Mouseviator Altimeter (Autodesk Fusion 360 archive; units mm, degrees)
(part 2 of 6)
sketch "Sketch1" plane through (-20, 10.05, 25) normal (0, -1, 0) x axis (1, 0, 0)
  line L1 (35.633, -31.4583) -> (38.9512, -31.4583)
  line L2 (35.3122, -31.4583) -> (35.633, -31.4583)
  line L3 (39.272, -31.4583) -> (35.3122, -31.4583)
  line L4 (38.9512, -31.4583) -> (39.272, -31.4583)
  line L5 (35.633, -28.5383) -> (35.3122, -28.5383)
  line L6 (38.9512, -28.5383) -> (35.633, -28.5383)
  line L7 (39.272, -28.5383) -> (38.9512, -28.5383)
  line L8 (35.3122, -28.5383) -> (39.272, -28.5383)
  line L9 (35.0708, -31.6363) -> (39.5135, -31.6363)
  line L10 (35.0708, -28.3602) -> (39.5135, -28.3602)
  line L11 (12.6239, -9.6591) -> (12.6239, -6.3409)
  line L12 (15.5439, -6.3409) -> (15.5439, -9.6591)
  line L13 (35.0124, -22.3491) -> (35.0004, -22.3785)
  line L14 (34.9323, -22.4564) -> (34.9111, -22.4657)
  line L15 (35.0979, -20.5925) -> (35.0505, -20.7749)
  line L16 (35.1569, -20.399) -> (35.0979, -20.5925)
  line L17 (36.6379, -21.3693) -> (36.6123, -21.2895)
  line L18 (34.97, -22.4255) -> (34.952, -22.443)
  line L19 (36.8842, -22.088) -> (36.8616, -22.0733)
  line L20 (36.5783, -21.1969) -> (36.5345, -21.0916)
  line L21 (36.6687, -21.4893) -> (36.6379, -21.3693)
  line L22 (36.7142, -21.799) -> (36.6929, -21.6882)
  line L23 (36.4146, -20.8483) -> (36.3364, -20.7116)
  line L24 (34.9578, -21.3696) -> (34.9526, -21.4836)
  line L25 (35.0129, -21.9844) -> (35.0308, -22.0958)
  line L26 (34.9677, -21.7892) -> (34.9793, -21.8532)
  line L27 (36.8182, -22.0307) -> (36.7977, -22.0028)
  line L28 (36.7431, -21.8932) -> (36.7142, -21.799)
  line L29 (37.806, -21.9706) -> (37.7866, -22.0028)
  line L30 (35.0359, -22.1943) -> (35.0294, -22.2789)
  line L31 (35.2212, -20.2151) -> (35.1569, -20.399)
  line L32 (34.9523, -21.5822) -> (34.9556, -21.666)
  line L33 (36.9302, -22.1041) -> (36.9071, -22.0983)
  line L34 (37.631, -22.1056) -> (37.4781, -22.1004)
  line L35 (37.7227, -22.0733) -> (37.7001, -22.088)
  line L36 (36.7782, -21.9706) -> (36.7431, -21.8932)
  line L37 (37.7001, -22.088) -> (37.6771, -22.0983)
  line L38 (37.4781, -22.1004) -> (37.2921, -22.0983)
  line L39 (37.7661, -22.0307) -> (37.7447, -22.0542)
  line L40 (36.6929, -21.6882) -> (36.6796, -21.5534)
  line L41 (36.6796, -21.5534) -> (36.6687, -21.4893)
  line L42 (36.2439, -20.5644) -> (36.137, -20.4092)
  line L43 (41.0503, -21.8878) -> (40.9731, -21.9719)
  line L44 (46.5349, -27.1956) -> (46.6729, -27.0478)
  line L45 (46.1507, -27.5452) -> (46.2718, -27.4445)
  line L46 (40.7882, -22.2157) -> (40.756, -22.2722)
  line L47 (40.4626, -22.6733) -> (40.4345, -22.6881)
  line L48 (36.5345, -21.0916) -> (36.4805, -20.9756)
  line L49 (45.0219, -28.1981) -> (45.0369, -28.1731)
  line L50 (45.8358, -27.767) -> (45.932, -27.7055)
  line L51 (41.6572, -21.3826) -> (41.5036, -21.4919)
  line L52 (40.1681, -22.6404) -> (39.9941, -22.5747)
  line L53 (37.8411, -21.8932) -> (37.806, -21.9706)
  line L54 (36.8395, -22.0542) -> (36.8182, -22.0307)
  line L55 (37.6771, -22.0983) -> (37.6541, -22.1041)
  line L56 (37.7447, -22.0542) -> (37.7227, -22.0733)
  line L57 (46.0368, -27.6322) -> (46.1507, -27.5452)
  line L58 (37.2921, -22.0983) -> (37.1061, -22.1004)
  line L59 (36.4805, -20.9756) -> (36.4146, -20.8483)
  line L60 (45.0564, -28.148) -> (45.0803, -28.1229)
  line L61 (45.0035, -28.271) -> (45.0052, -28.2473)
  line L62 (41.1407, -21.7973) -> (41.0503, -21.8878)
  line L63 (39.6142, -22.4255) -> (39.598, -22.404)
  line L64 (37.1061, -22.1004) -> (36.9533, -22.1056)
  line L65 (45.2665, -28.0054) -> (45.3719, -27.9652)
  line L66 (40.3809, -22.7046) -> (40.3559, -22.7064)
  line L67 (45.1086, -28.0982) -> (45.1787, -28.0502)
  line L68 (45.5023, -27.9287) -> (45.5635, -27.9067)
  line L69 (40.4345, -22.6881) -> (40.4072, -22.6985)
  line L70 (45.5635, -27.9067) -> (45.6764, -27.8557)
  line L71 (45.0052, -28.2473) -> (45.0114, -28.2229)
  line L72 (39.652, -22.4564) -> (39.6323, -22.443)
  line L73 (36.6123, -21.2895) -> (36.5783, -21.1969)
  line L74 (46.2718, -27.4445) -> (46.4006, -27.3279)
  line L75 (45.0369, -28.1731) -> (45.0564, -28.148)
  line L76 (41.5036, -21.4919) -> (41.3664, -21.5985)
  line L77 (36.7977, -22.0028) -> (36.7782, -21.9706)
  line L78 (37.6541, -22.1041) -> (37.631, -22.1056)
  line L79 (45.0114, -28.2229) -> (45.0219, -28.1981)
  line L80 (46.4006, -27.3279) -> (46.5349, -27.1956)
  line L81 (45.3719, -27.9652) -> (45.5023, -27.9287)
  line L82 (45.7505, -27.8166) -> (45.8358, -27.767)
  line L83 (37.7866, -22.0028) -> (37.7661, -22.0307)
  line L84 (36.9071, -22.0983) -> (36.8842, -22.088)
  line L85 (45.6764, -27.8557) -> (45.7505, -27.8166)
  line L86 (45.1787, -28.0502) -> (45.2665, -28.0054)
  line L87 (39.598, -22.404) -> (39.5838, -22.3785)
  line L88 (45.0803, -28.1229) -> (45.1086, -28.0982)
  line L89 (39.8185, -22.5131) -> (39.6732, -22.4657)
  line L90 (40.31, -22.6974) -> (40.1681, -22.6404)
  line L91 (40.6974, -22.3943) -> (40.6395, -22.4911)
  line L92 (45.932, -27.7055) -> (46.0368, -27.6322)
  line L93 (36.9533, -22.1056) -> (36.9302, -22.1041)
  line L94 (40.756, -22.2722) -> (40.6974, -22.3943)
  line L95 (40.8581, -22.1135) -> (40.7882, -22.2157)
  line L96 (40.9731, -21.9719) -> (40.9095, -22.0472)
  line L97 (36.8616, -22.0733) -> (36.8395, -22.0542)
  line L98 (40.3559, -22.7064) -> (40.3322, -22.704)
  line L99 (40.4914, -22.6541) -> (40.4626, -22.6733)
  line L100 (40.5801, -22.5698) -> (40.5207, -22.6305)
  line L101 (41.9942, -21.1728) -> (41.8267, -21.2723)
  line L102 (44.6267, -24.8888) -> (44.7002, -24.7841)
  line L103 (42.5014, -22.4249) -> (42.5294, -22.27)
  line L104 (44.938, -24.3736) -> (45.0189, -24.2034)
  line L105 (42.2262, -23.8286) -> (42.1059, -23.7343)
  line L106 (43.5976, -23.6623) -> (43.4963, -23.7149)
  line L107 (40.5207, -22.6305) -> (40.4914, -22.6541)
  line L108 (40.9095, -22.0472) -> (40.8581, -22.1135)
  line L109 (41.2462, -21.7002) -> (41.1407, -21.7973)
  line L110 (41.3664, -21.5985) -> (41.2462, -21.7002)
  line L111 (42.571, -21.9102) -> (42.5817, -21.7082)
  line L112 (42.0518, -23.6218) -> (42.0505, -23.5901)
  line L113 (42.0642, -23.6764) -> (42.0564, -23.6507)
  line L114 (42.3701, -23.9465) -> (42.2262, -23.8286)
  line L115 (42.47, -22.5648) -> (42.5014, -22.4249)
  line L116 (42.3693, -22.89) -> (42.4027, -22.7972)
  line L117 (39.9941, -22.5747) -> (39.8185, -22.5131)
  line L118 (42.0752, -23.699) -> (42.0642, -23.6764)
  line L119 (42.0505, -23.5901) -> (42.0527, -23.5556)
  line L120 (42.6436, -24.1837) -> (42.625, -24.1699)
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  parallel L8 L10
  dimension "d124" diameter = 18
  dimension "d189" = 0.3 (= "StepperTightness")
  dimension "d190" = 0.3 (= "d189")
extrude "Extrude1" new body sketch "Sketch1" to an object offset 1.25
sketch "Sketch1" plane through (14.0839, 18.05, 42) normal (0, -1, 0) x axis (-1, 0, 0)
  line L1 (21.46, 26.6591) -> (21.46, 23.3409)
  line L2 (18.54, 23.3409) -> (18.54, 26.6591)
  line L3 (25.078, 31.0517) -> (24.9341, 31.1697)
  line L4 (24.8138, 31.264) -> (24.797, 31.2799)
  line L5 (25.2093, 32.5734) -> (25.2373, 32.7283)
  line L6 (24.9341, 31.1697) -> (24.8138, 31.264)
  line L7 (25.3329, 30.8284) -> (25.2192, 30.9305)
  line L8 (24.0743, 33.3998) -> (23.9541, 33.2981)
  line L9 (25.261, 32.9005) -> (25.2789, 33.0881)
  line L10 (24.5346, 33.726) -> (24.3651, 33.6157)
  line L11 (25.2789, 33.0881) -> (25.2896, 33.2901)
  line L12 (24.7893, 31.5617) -> (24.8278, 31.6525)
  line L13 (24.3651, 33.6157) -> (24.2115, 33.5064)
  line L14 (24.2115, 33.5064) -> (24.0743, 33.3998)
  line L15 (24.7664, 31.4799) -> (24.7893, 31.5617)
  line L16 (25.1779, 32.4335) -> (25.2093, 32.5734)
  line L17 (24.9591, 31.8628) -> (24.9919, 31.919)
  line L18 (23.9541, 33.2981) -> (23.8486, 33.2009)
  line L19 (24.7021, 33.8255) -> (24.5346, 33.726)
  line L20 (25.2373, 32.7283) -> (25.261, 32.9005)
  line L21 (25.2192, 30.9305) -> (25.078, 31.0517)
  line L22 (25.0455, 32.0306) -> (25.0772, 32.1083)
  line L23 (25.2896, 33.2901) -> (25.2921, 33.4849)
  line L24 (24.9919, 31.919) -> (25.0455, 32.0306)
  line L25 (25.1448, 32.3099) -> (25.1779, 32.4335)
  line L26 (28.6945, 24.1572) -> (28.7916, 24.1746)
  line L27 (29.4726, 24.3941) -> (29.644, 24.4724)
  line L28 (29.1634, 25.7247) -> (29.0265, 25.7675)
  line L29 (29.4726, 25.6059) -> (29.3116, 25.6715)
  line L30 (24.7643, 31.3476) -> (24.7597, 31.3764)
  line L31 (28.1751, 24.1453) -> (28.2879, 24.147)
  line L32 (27.8469, 25.9926) -> (27.8371, 26.0144)
  line L33 (27.8371, 26.0144) -> (27.8317, 26.0368)
  line L34 (25.0772, 32.1083) -> (25.1106, 32.201)
  line L35 (28.6115, 24.1458) -> (28.6945, 24.1572)
  line L36 (29.644, 24.4724) -> (29.8242, 24.5641)
  line L37 (27.9289, 24.0832) -> (27.9599, 24.0985)
  line L38 (24.7597, 31.3764) -> (24.7584, 31.4082)
  line L39 (27.995, 25.8879) -> (27.9599, 25.9014)
  line L40 (28.2879, 24.147) -> (28.423, 24.1367)
  line L41 (29.9942, 25.3406) -> (29.8242, 25.4359)
  line L42 (28.7916, 25.8254) -> (28.6945, 25.8428)
  line L43 (28.488, 25.8636) -> (28.423, 25.8633)
  line L44 (27.8317, 26.0368) -> (27.8102, 26.1882)
  line L45 (27.995, 24.1121) -> (28.0773, 24.1332)
  line L46 (28.7916, 24.1746) -> (28.903, 24.1995)
  line L47 (29.0265, 25.7675) -> (28.903, 25.8005)
  line L48 (29.3116, 25.6715) -> (29.1634, 25.7247)
  line L49 (29.644, 25.5276) -> (29.4726, 25.6059)
  line L50 (24.7584, 31.4082) -> (24.7606, 31.4427)
  line L51 (27.9289, 25.9168) -> (27.902, 25.9337)
  line L52 (28.903, 25.8005) -> (28.7916, 25.8254)
  line L53 (27.8102, 26.1882) -> (27.78, 26.3718)
  line L54 (25.1106, 32.201) -> (25.1448, 32.3099)
  line L55 (24.8826, 31.751) -> (24.9591, 31.8628)
  line L56 (27.7456, 26.5546) -> (27.714, 26.7042)
  line L57 (27.861, 25.9718) -> (27.8469, 25.9926)
  line L58 (28.2879, 25.853) -> (28.1751, 25.8547)
  line L59 (24.7721, 31.3218) -> (24.7643, 31.3476)
  line L60 (27.9599, 24.0985) -> (27.995, 24.1121)
  line L61 (29.0265, 24.2325) -> (29.1634, 24.2753)
  line L62 (28.0773, 24.1332) -> (28.1751, 24.1453)
  line L63 (28.6115, 25.8542) -> (28.488, 25.8636)
  line L64 (24.8278, 31.6525) -> (24.8826, 31.751)
  line L65 (27.714, 26.7042) -> (27.7114, 26.7272)
  line L66 (24.797, 31.2799) -> (24.7831, 31.2992)
  line L67 (27.78, 26.3718) -> (27.7456, 26.5546)
  line L68 (27.902, 25.9337) -> (27.8794, 25.9521)
  line L69 (29.3116, 24.3285) -> (29.4726, 24.3941)
  line L70 (27.902, 24.0662) -> (27.9289, 24.0832)
  line L71 (27.8794, 24.0478) -> (27.902, 24.0662)
  line L72 (28.488, 24.1364) -> (28.6115, 24.1458)
  line L73 (27.8794, 25.9521) -> (27.861, 25.9718)
  line L74 (28.423, 24.1367) -> (28.488, 24.1364)
  line L75 (28.903, 24.1995) -> (29.0265, 24.2325)
  line L76 (29.1634, 24.2753) -> (29.3116, 24.3285)
  line L77 (28.0773, 25.8667) -> (27.995, 25.8879)
  line L78 (28.1751, 25.8547) -> (28.0773, 25.8667)
  line L79 (28.423, 25.8633) -> (28.2879, 25.853)
  line L80 (24.7606, 31.4427) -> (24.7664, 31.4799)
  line L81 (24.7831, 31.2992) -> (24.7721, 31.3218)
  line L82 (27.9599, 25.9014) -> (27.9289, 25.9168)
  line L83 (28.6945, 25.8428) -> (28.6115, 25.8542)
  line L84 (29.8242, 24.5641) -> (29.9942, 24.6594)
  line L85 (29.8242, 25.4359) -> (29.644, 25.5276)
  line L86 (29.3808, 22.0495) -> (29.2428, 22.1973)
  line L87 (27.2937, 21.4229) -> (27.3898, 21.4008)
  line L88 (27.8866, 23.0519) -> (27.8165, 23.0999)
  line L89 (28.2197, 21.1915) -> (28.3629, 21.1849)
  line L90 (27.78, 23.6282) -> (27.8102, 23.8117)
  line L91 (27.861, 24.0281) -> (27.8794, 24.0478)
  line L92 (27.3898, 21.4008) -> (27.4963, 21.3638)
  line L93 (28.7447, 22.6339) -> (28.6399, 22.7072)
  line L94 (28.6941, 21.1908) -> (28.8819, 21.2058)
  line L95 (27.7882, 23.1246) -> (27.7643, 23.1497)
  line L96 (28.5437, 22.7687) -> (28.4584, 22.8183)
  line L97 (27.0785, 21.4104) -> (27.1061, 21.4199)
  line L98 (29.0827, 21.2303) -> (29.275, 21.2617)
  line L99 (27.7448, 23.1748) -> (27.7298, 23.1998)
  line L100 (28.0798, 22.9669) -> (27.9744, 23.0071)
  line L101 (27.1715, 21.4305) -> (27.2092, 21.4312)
  line L102 (28.0923, 21.2028) -> (28.2197, 21.1915)
  line L103 (28.8587, 22.5469) -> (28.7447, 22.6339)
  line L104 (27.7643, 23.1497) -> (27.7448, 23.1748)
  line L105 (27.8102, 23.8117) -> (27.8317, 23.9631)
  line L106 (29.2428, 22.1973) -> (29.1085, 22.3296)
  line L107 (27.8317, 23.9631) -> (27.8371, 23.9856)
  line L108 (26.6659, 20.7602) -> (26.7467, 20.89)
  line L109 (26.6491, 20.7165) -> (26.6556, 20.7395)
  line L110 (27.0175, 21.3664) -> (27.0341, 21.3834)
  line L111 (28.5204, 21.1843) -> (28.6941, 21.1908)
  line L112 (27.0341, 21.3834) -> (27.0545, 21.3982)
  line L113 (27.9791, 21.2175) -> (28.0923, 21.2028)
  line L114 (27.6807, 21.2854) -> (27.8, 21.252)
  line L115 (27.8371, 23.9856) -> (27.8469, 24.0073)
  line L116 (27.4963, 21.3638) -> (27.6197, 21.308)
  line L117 (27.9744, 23.0071) -> (27.8866, 23.0519)
  line L118 (27.2092, 21.4312) -> (27.2937, 21.4229)
  line L119 (27.8165, 23.0999) -> (27.7882, 23.1246)
  line L120 (27.0047, 21.3471) -> (27.0175, 21.3664)
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extrude "Extrude1" new body sketch "Sketch1" to an object offset 1.25
work_plane "WorkPlane1" AlongDistance 0
sketch "Gear" plane through (-20, 10.05, 25) normal (0, -1, 0) x axis (1, 0, 0)
  line L1 (20.549, -33.1051) -> (20.5779, -33.1993)
  line L2 (23.566, -32.8848) -> (23.6174, -32.9511)
  line L3 (22.3049, -33.8984) -> (22.3233, -33.7561)
  line L4 (20.6235, -33.509) -> (20.6542, -33.629)
  line L5 (25.1106, -32.2011) -> (25.0771, -32.1083)
  line L6 (22.702, -32.4236) -> (22.876, -32.3579)
  line L7 (22.1352, -34.5993) -> (22.1942, -34.4058)
  line L8 (22.3811, -32.5326) -> (22.5264, -32.4852)
  line L9 (20.9557, -34.2867) -> (21.0482, -34.4339)
  line L10 (20.5779, -33.1993) -> (20.5992, -33.3101)
  line L11 (20.4526, -32.9441) -> (20.474, -32.9676)
  line L12 (23.6174, -32.9511) -> (23.681, -33.0264)
  line L13 (22.876, -32.3579) -> (23.0179, -32.3008)
  line L14 (23.1423, -32.3102) -> (23.1705, -32.325)
  line L15 (22.2416, -34.2234) -> (22.2782, -34.0535)
  line L16 (22.2562, -32.804) -> (22.2627, -32.7194)
  line L17 (23.0179, -32.3008) -> (23.0401, -32.2943)
  line L18 (21.0482, -34.4339) -> (21.1551, -34.589)
  line L19 (19.615, -32.9) -> (19.6381, -32.8941)
  line L20 (23.0888, -32.2937) -> (23.1151, -32.2998)
  line L21 (20.385, -32.9) -> (20.408, -32.9103)
  line L22 (23.2286, -32.3678) -> (23.288, -32.4285)
  line L23 (22.27, -32.6824) -> (22.2797, -32.6492)
  line L24 (22.2797, -32.6492) -> (22.2917, -32.6198)
  line L25 (22.3244, -33.209) -> (22.3128, -33.1451)
  line L26 (22.3395, -33.5147) -> (22.3398, -33.4161)
  line L27 (20.8116, -34.0227) -> (20.8775, -34.15)
  line L28 (22.3221, -32.5728) -> (22.3401, -32.5553)
  line L29 (20.6125, -33.4449) -> (20.6235, -33.509)
  line L30 (20.5139, -33.0277) -> (20.549, -33.1051)
  line L31 (22.3398, -33.4161) -> (22.3366, -33.3323)
  line L32 (22.2792, -33.0138) -> (22.2613, -32.9025)
  line L33 (22.3598, -32.5419) -> (22.3811, -32.5326)
  line L34 (22.3128, -33.1451) -> (22.2792, -33.0138)
  line L35 (22.2917, -32.6198) -> (22.3059, -32.5943)
  line L36 (23.681, -33.0264) -> (23.7582, -33.1105)
  line L37 (22.1942, -34.4058) -> (22.2416, -34.2234)
  line L38 (20.5992, -33.3101) -> (20.6125, -33.4449)
  line L39 (23.0401, -32.2943) -> (23.0638, -32.2919)
  line L40 (22.3233, -33.7561) -> (22.3343, -33.6287)
  line L41 (23.1993, -32.3442) -> (23.2286, -32.3678)
  line L42 (22.2627, -32.7194) -> (22.27, -32.6824)
  line L43 (22.2782, -34.0535) -> (22.3049, -33.8984)
  line L44 (20.8775, -34.15) -> (20.9557, -34.2867)
  line L45 (22.0709, -34.7832) -> (22.1352, -34.5993)
  line L46 (23.0638, -32.2919) -> (23.0888, -32.2937)
  line L47 (20.4945, -32.9955) -> (20.5139, -33.0277)
  line L48 (20.3619, -32.8941) -> (20.385, -32.9)
  line L49 (20.3389, -32.8927) -> (20.3619, -32.8941)
  line L50 (19.814, -32.8978) -> (20, -32.9)
  line L51 (25.2373, -32.7283) -> (25.2093, -32.5734)
  line L52 (24.0743, -33.3998) -> (24.2115, -33.5064)
  line L53 (22.3059, -32.5943) -> (22.3221, -32.5728)
  line L54 (22.5264, -32.4852) -> (22.702, -32.4236)
  line L55 (22.3366, -33.3323) -> (22.3244, -33.209)
  line L56 (22.3401, -32.5553) -> (22.3598, -32.5419)
  line L57 (22.3343, -33.6287) -> (22.3395, -33.5147)
  line L58 (22.2613, -32.9025) -> (22.2562, -32.804)
  line L59 (18.7233, -34.7507) -> (18.8449, -34.589)
  line L60 (20, -32.9) -> (20.186, -32.8978)
  line L61 (19.4008, -33.3101) -> (19.4221, -33.1993)
  line L62 (19.2424, -33.9067) -> (19.2862, -33.8013)
  line L63 (20.6542, -33.629) -> (20.6798, -33.7088)
  line L64 (20.7138, -33.8013) -> (20.7576, -33.9067)
  line L65 (20.408, -32.9103) -> (20.4305, -32.925)
  line L66 (21.1551, -34.589) -> (21.2767, -34.7507)
  line L67 (20.4305, -32.925) -> (20.4526, -32.9441)
  line L68 (17.7438, -32.804) -> (17.7387, -32.9025)
  line L69 (17.6605, -33.5147) -> (17.6657, -33.6287)
  line L70 (20.474, -32.9676) -> (20.4945, -32.9955)
  line L71 (18.8449, -34.589) -> (18.9518, -34.4339)
  line L72 (17.7083, -32.6198) -> (17.7203, -32.6492)
  line L73 (17.298, -32.4236) -> (17.4736, -32.4852)
  line L74 (16.8295, -32.325) -> (16.8577, -32.3102)
  line L75 (17.7373, -32.7194) -> (17.7438, -32.804)
  line L76 (17.73, -32.6824) -> (17.7373, -32.7194)
  line L77 (17.7208, -33.0138) -> (17.6872, -33.1451)
  line L78 (17.6779, -32.5728) -> (17.6941, -32.5943)
  line L79 (16.8577, -32.3102) -> (16.8849, -32.2998)
  line L80 (17.7218, -34.0535) -> (17.7584, -34.2234)
  line L81 (20.186, -32.8978) -> (20.3389, -32.8927)
  line L82 (19.4861, -33.0277) -> (19.5055, -32.9955)
  line L83 (18.9518, -34.4339) -> (19.0443, -34.2867)
  line L84 (21.2767, -34.7507) -> (21.4, -34.9015)
  line L85 (18.6, -34.9015) -> (18.7233, -34.7507)
  line L86 (17.8058, -34.4058) -> (17.8648, -34.5993)
  line L87 (17.6634, -33.3323) -> (17.6602, -33.4161)
  line L88 (17.4736, -32.4852) -> (17.6189, -32.5326)
  line L89 (19.451, -33.1051) -> (19.4861, -33.0277)
  line L90 (19.5055, -32.9955) -> (19.526, -32.9676)
  line L91 (16.9599, -32.2943) -> (16.9821, -32.3008)
  line L92 (16.7714, -32.3678) -> (16.8007, -32.3442)
  line L93 (19.1225, -34.15) -> (19.1884, -34.0227)
  line L94 (17.6767, -33.7561) -> (17.6951, -33.8984)
  line L95 (16.5361, -32.7261) -> (16.5947, -32.604)
  line L96 (17.8648, -34.5993) -> (17.9291, -34.7832)
  line L97 (19.5695, -32.925) -> (19.592, -32.9103)
  line L98 (19.3202, -33.7088) -> (19.3458, -33.629)
  line L99 (19.592, -32.9103) -> (19.615, -32.9)
  line L100 (17.6602, -33.4161) -> (17.6605, -33.5147)
  line L101 (19.6612, -32.8927) -> (19.814, -32.8978)
  line L102 (19.2862, -33.8013) -> (19.3202, -33.7088)
  line L103 (20.6798, -33.7088) -> (20.7138, -33.8013)
  line L104 (19.6381, -32.8941) -> (19.6612, -32.8927)
  line L105 (19.4221, -33.1993) -> (19.451, -33.1051)
  line L106 (19.0443, -34.2867) -> (19.1225, -34.15)
  line L107 (16.5947, -32.604) -> (16.6526, -32.5072)
  line L108 (20.7576, -33.9067) -> (20.8116, -34.0227)
  line L109 (19.3766, -33.509) -> (19.3875, -33.4449)
  line L110 (19.526, -32.9676) -> (19.5474, -32.9441)
  line L111 (19.3875, -33.4449) -> (19.4008, -33.3101)
  line L112 (19.1884, -34.0227) -> (19.2424, -33.9067)
  line L113 (17.6657, -33.6287) -> (17.6767, -33.7561)
  line L114 (19.5474, -32.9441) -> (19.5695, -32.925)
  line L115 (17.7584, -34.2234) -> (17.8058, -34.4058)
  line L116 (19.3458, -33.629) -> (19.3766, -33.509)
  line L117 (16.6526, -32.5072) -> (16.712, -32.4285)
  line L118 (17.6951, -33.8984) -> (17.7218, -34.0535)
  line L119 (16.5039, -32.7826) -> (16.5361, -32.7261)
  line L120 (16.434, -32.8848) -> (16.5039, -32.7826)
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  dimension "d312" = 0.1 (= "GluePressFitToll")
extrude "Extrude3" sketch "Gear" to an object bodies "10K Needle Gear"
work_plane "WorkPlane1" AlongDistance 0
sketch "Sketch2" plane through (20, 18.05, 10) normal (0, -1, 0) x axis (1, 0, 0)
  line L1 (-27.3347, -4.8906) -> (-27.2653, -4.9812)
  line L2 (-27.0175, -6.3665) -> (-27.0341, -6.3835)
  line L3 (-26.6659, -5.7603) -> (-26.7467, -5.8901)
  line L4 (-27.7268, -4.2053) -> (-27.6459, -4.3754)
  line L5 (-26.6465, -5.6917) -> (-26.6491, -5.7167)
  line L6 (-26.5538, -3.5548) -> (-26.7015, -3.5004)
  line L7 (-27.0048, -6.3472) -> (-27.0175, -6.3665)
  line L8 (-28.7447, -7.634) -> (-28.6399, -7.7073)
  line L9 (-27.1371, -6.4268) -> (-27.1716, -6.4306)
  line L10 (-26.6771, -5.5741) -> (-26.6632, -5.6058)
  line L11 (-25.5182, -4.193) -> (-25.5538, -4.1809)
  line L12 (-24.9342, -3.8304) -> (-25.078, -3.9484)
  line L13 (-26.7015, -3.5004) -> (-26.8669, -3.4471)
  line L14 (-25.8975, -3.9246) -> (-25.9471, -3.8826)
  line L15 (-25.6304, -4.1442) -> (-25.7131, -4.0905)
  line L16 (-26.9328, -6.2123) -> (-27.0048, -6.3472)
  line L17 (-25.3515, -4.1855) -> (-25.373, -4.1958)
  line L18 (-26.6556, -5.7396) -> (-26.6659, -5.7603)
  line L19 (-26.6953, -5.5412) -> (-26.6771, -5.5741)
  line L20 (-26.8669, -3.4471) -> (-27.0486, -3.3969)
  line L21 (-25.3329, -4.1717) -> (-25.3515, -4.1855)
  line L22 (-26.3055, -3.6642) -> (-26.4214, -3.61)
  line L23 (-26.6535, -5.6361) -> (-26.648, -5.6648)
  line L24 (-26.7447, -5.4721) -> (-26.6953, -5.5412)
  line L25 (-27.1061, -6.42) -> (-27.1371, -6.4268)
  line L26 (-25.9471, -3.8826) -> (-26.0477, -3.8104)
  line L27 (-25.4846, -4.2012) -> (-25.5182, -4.193)
  line L28 (-24.797, -3.7202) -> (-24.8138, -3.7361)
  line L29 (-27.5647, -4.5291) -> (-27.4854, -4.6651)
  line L30 (-27.6459, -4.3754) -> (-27.5647, -4.5291)
  line L31 (-26.8416, -6.0501) -> (-26.9328, -6.2123)
  line L32 (-26.0477, -3.8104) -> (-26.1187, -3.7658)
  line L33 (-27.2022, -5.057) -> (-27.1458, -5.1191)
  line L34 (-26.648, -5.6648) -> (-26.6465, -5.6917)
  line L35 (-27.0573, -5.2057) -> (-27.0073, -5.2472)
  line L36 (-27.1458, -5.1191) -> (-27.0573, -5.2057)
  line L37 (-27.0073, -5.2472) -> (-26.8972, -5.3262)
  line L38 (-26.8119, -5.4) -> (-26.7447, -5.4721)
  line L39 (-27.2653, -4.9812) -> (-27.2022, -5.057)
  line L40 (-27.4854, -4.6651) -> (-27.4081, -4.7859)
  line L41 (-25.3972, -4.2027) -> (-25.4239, -4.206)
  line L42 (-26.1187, -3.7658) -> (-26.2042, -3.7167)
  line L43 (-26.6632, -5.6058) -> (-26.6535, -5.6361)
  line L44 (-27.806, -4.0191) -> (-27.7268, -4.2053)
  line L45 (-27.0341, -6.3835) -> (-27.0545, -6.3983)
  line L46 (-27.2092, -6.4313) -> (-27.2937, -6.423)
  line L47 (-27.875, -3.8369) -> (-27.806, -4.0191)
  line L48 (-27.0486, -3.3969) -> (-27.2456, -3.3513)
  line L49 (-25.4531, -4.2055) -> (-25.4846, -4.2012)
  line L50 (-27.4081, -4.7859) -> (-27.3347, -4.8906)
  line L51 (-27.0785, -6.4105) -> (-27.1061, -6.42)
  line L52 (-27.8819, -6.2344) -> (-27.9791, -6.2176)
  line L53 (-28.0923, -6.2029) -> (-28.2197, -6.1917)
  line L54 (-25.4239, -4.206) -> (-25.4531, -4.2055)
  line L55 (-26.6491, -5.7167) -> (-26.6556, -5.7396)
  line L56 (-25.5538, -4.1809) -> (-25.6304, -4.1442)
  line L57 (-25.8006, -4.0194) -> (-25.8975, -3.9246)
  line L58 (-26.7467, -5.8901) -> (-26.8416, -6.0501)
  line L59 (-26.8972, -5.3262) -> (-26.8119, -5.4)
  line L60 (-27.0545, -6.3983) -> (-27.0785, -6.4105)
  line L61 (-25.2373, -2.2718) -> (-25.2093, -2.4267)
  line L62 (-24.5346, -1.2741) -> (-24.7021, -1.1746)
  line L63 (-25.1779, -2.5666) -> (-25.1448, -2.6902)
  line L64 (-24.7831, -3.7009) -> (-24.797, -3.7202)
  line L65 (-27.2456, -3.3513) -> (-27.4371, -3.315)
  line L66 (-25.373, -4.1958) -> (-25.3972, -4.2027)
  line L67 (-25.0772, -2.8918) -> (-25.0455, -2.9694)
  line L68 (-25.2921, -1.5152) -> (-25.2896, -1.71)
  line L69 (-24.7597, -3.6237) -> (-24.7643, -3.6525)
  line L70 (-26.4214, -3.61) -> (-26.5538, -3.5548)
  line L71 (-25.078, -3.9484) -> (-25.2192, -4.0696)
  line L72 (-25.2093, -2.4267) -> (-25.1779, -2.5666)
  line L73 (-24.8826, -3.2491) -> (-24.8278, -3.3476)
  line L74 (-26.2042, -3.7167) -> (-26.3055, -3.6642)
  line L75 (-25.2192, -4.0696) -> (-25.3329, -4.1717)
  line L76 (-24.8138, -3.7361) -> (-24.9342, -3.8304)
  line L77 (-25.261, -2.0996) -> (-25.2373, -2.2718)
  line L78 (-25.1448, -2.6902) -> (-25.1106, -2.799)
  line L79 (-24.3651, -1.3844) -> (-24.5346, -1.2741)
  line L80 (-25.7131, -4.0905) -> (-25.8006, -4.0194)
  line L81 (-24.8278, -3.3476) -> (-24.7893, -3.4384)
  line L82 (-25.2789, -1.912) -> (-25.261, -2.0996)
  line L83 (-24.7606, -3.5574) -> (-24.7584, -3.5919)
  line L84 (-23.9541, -1.702) -> (-24.0743, -1.6003)
  line L85 (-25.0455, -2.9694) -> (-24.9919, -3.0811)
  line L86 (-24.7665, -3.5202) -> (-24.7606, -3.5574)
  line L87 (-24.9919, -3.0811) -> (-24.9591, -3.1373)
  line L88 (-23.6174, -2.049) -> (-23.681, -1.9737)
  line L89 (-23.8486, -1.7992) -> (-23.9541, -1.702)
  line L90 (-22.2562, -2.1961) -> (-22.2627, -2.2808)
  line L91 (-22.2797, -2.3509) -> (-22.2918, -2.3803)
  line L92 (-24.7643, -3.6525) -> (-24.7721, -3.6782)
  line L93 (-23.681, -1.9737) -> (-23.7582, -1.8896)
  line L94 (-25.2896, -1.71) -> (-25.2789, -1.912)
  line L95 (-24.9591, -3.1373) -> (-24.8826, -3.2491)
  line L96 (-24.7893, -3.4384) -> (-24.7665, -3.5202)
  line L97 (-24.2116, -1.4937) -> (-24.3651, -1.3844)
  line L98 (-24.7584, -3.5919) -> (-24.7597, -3.6237)
  line L99 (-22.2627, -2.2808) -> (-22.27, -2.3177)
  line L100 (-23.7582, -1.8896) -> (-23.8486, -1.7992)
  line L101 (-22.2792, -1.9863) -> (-22.2613, -2.0976)
  line L102 (-22.2613, -2.0976) -> (-22.2562, -2.1961)
  line L103 (-23.0889, -2.7064) -> (-23.1151, -2.7003)
  line L104 (-22.3128, -1.855) -> (-22.2792, -1.9863)
  line L105 (-22.306, -2.4058) -> (-22.3221, -2.4273)
  line L106 (-24.0743, -1.6003) -> (-24.2116, -1.4937)
  line L107 (-24.7721, -3.6782) -> (-24.7831, -3.7009)
  line L108 (-23.0179, -2.6993) -> (-23.0401, -2.7058)
  line L109 (-23.566, -2.1153) -> (-23.6174, -2.049)
  line L110 (-25.1106, -2.799) -> (-25.0772, -2.8918)
  line L111 (-23.3474, -2.4929) -> (-23.4053, -2.3961)
  line L112 (-22.8761, -2.6422) -> (-23.0179, -2.6993)
  line L113 (-23.1993, -2.6559) -> (-23.2286, -2.6323)
  line L114 (-23.1424, -2.6899) -> (-23.1705, -2.6751)
  line L115 (-23.4961, -2.2175) -> (-23.566, -2.1153)
  line L116 (-23.0401, -2.7058) -> (-23.0638, -2.7082)
  line L117 (-23.4053, -2.3961) -> (-23.4639, -2.274)
  line L118 (-22.3811, -2.4675) -> (-22.5264, -2.5149)
  line L119 (-22.5264, -2.5149) -> (-22.702, -2.5765)
  line L120 (-23.2286, -2.6323) -> (-23.288, -2.5716)
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  dimension "d355" distance = 0.1 (= "GluePressFitToll")
extrude "Extrude3" new body sketch "Sketch2" to an object offset 1.5 bodies "1K Needle Gear"
component_insert "Component Insert2"
joint "Assemble2" alignAngle -90 alignOffsetX 0 alignOffsetY 0 alignOffsetZ 0
extrude "Extrude4" add of existing geometry blind 2
fillet "Fillet1" radius 0.5
decal "Decal1"
sketch "Motor Cutouts" plane through (0, 39, 0) normal (0, 1, 0) x axis (-1, 0, 0)
  line L1 (36.4994, 34.1766) -> (41.1157, 22.3885)
  line L2 (26.5185, 40.8706) -> (34.1546, 36.8093)
  line L3 (-24.1231, 41.4655) -> (24.1331, 41.4655)
  line L4 (-33.6166, 37.0564) -> (-26.5251, 40.8618)
  line L5 (-41.1157, 22.3885) -> (-36.4994, 34.1766)
  line L6 (-41.4655, -20.5361) -> (-41.4655, 20.5361)
  line L7 (-36.4994, -34.1766) -> (-41.1157, -22.3885)
  line L8 (-23.2139, -41.1177) -> (-33.6166, -37.0564)
  curve K1 (-21.3665, -41.4655) -> (-21.9088, -41.4365)
  line L9 (28.9018, -41.4655) -> (-21.3665, -41.4655)
  line L10 (41.4655, 20.5361) -> (41.4655, -28.9018)
  curve K2 (41.4365, 21.0784) -> (41.4655, 20.5361)
  line L11 (-3.0839, 41.8845) -> (14.9161, 41.8845)
  line L12 (-3.0839, 35.8845) -> (-3.0839, 41.8845)
  line L13 (14.9161, 35.8845) -> (-3.0839, 35.8845)
  line L14 (14.9161, 41.8845) -> (14.9161, 35.8845)
  line L15 (0.1458, 35.8845) -> (14.9161, 35.8845)
  line L16 (-36.1766, -13.9983) -> (-36.1766, 4.0017)
  line L17 (-42.1766, -13.9983) -> (-36.1766, -13.9983)
  line L18 (-42.1766, 4.0017) -> (-42.1766, -13.9983)
  line L19 (-36.1766, 4.0017) -> (-42.1766, 4.0017)
  line L20 (-15.7982, -4.9983) -> (-24.6171, -4.9983)
  arc A1 centre (36.3855, 20.5361) radius 5.08 clockwise from (41.1157, 22.3885) to (41.4365, 21.0784)
  arc A2 centre (31.7692, 32.3242) radius 5.08 clockwise from (34.1546, 36.8093) to (36.4994, 34.1766)
  arc A3 centre (24.1331, 36.3855) radius 5.08 clockwise from (24.1331, 41.4655) to (26.5185, 40.8706)
  arc A4 centre (-24.1231, 36.3855) radius 5.08 clockwise from (-26.5251, 40.8618) to (-24.1231, 41.4655)
  arc A5 centre (-31.7692, 32.3242) radius 5.08 clockwise from (-36.4994, 34.1766) to (-33.6166, 37.0564)
  arc A6 centre (-36.3855, 20.5361) radius 5.08 clockwise from (-41.4655, 20.5361) to (-41.1157, 22.3885)
  arc A7 centre (-36.3855, -20.5361) radius 5.08 clockwise from (-41.1157, -22.3885) to (-41.4655, -20.5361)
  arc A8 centre (-31.7692, -32.3242) radius 5.08 clockwise from (-33.6166, -37.0564) to (-36.4994, -34.1766)
  arc A9 centre (-21.3665, -36.3855) radius 5.08 clockwise from (-21.9088, -41.4365) to (-23.2139, -41.1177)
  arc A10 centre (28.9018, -28.9018) radius 12.5637 clockwise from (41.4655, -28.9018) to (28.9018, -41.4655)
  circle C1 centre (-18.76, -36.96) radius 1
  circle C2 centre (31.4309, 31.4309) radius 2.159
  circle C3 centre (-18.76, 36.96) radius 1
  circle C4 centre (18.76, 36.96) radius 1
  circle C5 centre (0, 0) radius 5
  circle C6 centre (-31.4309, -31.4309) radius 2.159
  circle C7 centre (-31.4309, 31.4309) radius 2.159
  circle C8 centre (-24.6171, -4.9983) radius 13.4
  circle C9 centre (5.9161, 24.325) radius 13.4
  circle C10 centre (-24.6171, -4.9983) radius 14.65
  circle C11 centre (5.9161, 24.325) radius 14.65
  circle C12 centre (-7.1948, -17.5539) radius 1.4
  circle C13 centre (36.96, 18.76) radius 1
  circle C14 centre (17.5539, 7.1948) radius 1.4
  circle C15 centre (-36.96, 18.76) radius 1
  circle C16 centre (-36.96, -18.76) radius 1
  circle C17 centre (30.9023, -30.9023) radius 5.5
  point P47 (-3.0839, 35.8845)
  point P48 (14.9161, 35.8845)
  point P51 (-36.1766, -13.9983)
  point P50 (-36.1766, 4.0017)
  point P41 (-24.6171, -4.9983)
  point P59 (-24.6171, -4.9983)
  point P45 (14.9161, 41.8845)
  point P46 (-3.0839, 41.8845)
  point P53 (-42.1766, 4.0017)
  point P52 (-42.1766, -13.9983)
  perpendicular L11 L12
  parallel L11 L13
  parallel L12 L14
  coincident C11 P47
  coincident C11 P48
  horizontal L15
  parallel L16 L18
  parallel L17 L19
  coincident C10 P51
  coincident C10 P50
  coincident P41 P59
  horizontal L20
  perpendicular L18 L19
  dimension "d173" = 1.25
  dimension "d174" = 1.25 (= "d173")
  dimension "d175" angle L14 L15 = 90
  dimension "d176" distance P45 P46 = 18
  dimension "d177" distance P45 P48 = 6
  dimension "d303" angle L16 L20 = 90
  dimension "d304" distance P50 P53 = 6 (= "d177")
  dimension "d305" distance P52 P53 = 18 (= "d176")
extrude "Extrude10" cut sketch "Motor Cutouts" profile of C10 C11 L11 L12 L13 L14 L16 L17 L18 L19 to an object
sketch "Standoffs" plane through (0, 36.5, 0) normal (0, -1, 0) x axis (1, 0, 0)
  curve K1 (-41.4655, 20.5361) -> (-41.4365, 21.0784)
  line L1 (-41.4655, -28.9018) -> (-41.4655, 20.5361)
  line L2 (21.3665, -41.4655) -> (-28.9018, -41.4655)
  curve K2 (21.9088, -41.4365) -> (21.3665, -41.4655)
  line L3 (33.6166, -37.0564) -> (23.2139, -41.1177)
  line L4 (41.1157, -22.3885) -> (36.4994, -34.1766)
  line L5 (41.4655, 20.5361) -> (41.4655, 4.0017)
  line L6 (36.4994, 34.1766) -> (41.1157, 22.3885)
  line L7 (26.5251, 40.8618) -> (33.6166, 37.0564)
  line L8 (-24.1331, 41.4655) -> (-14.9161, 41.4655)
  line L9 (-34.1546, 36.8093) -> (-26.5185, 40.8706)
  line L10 (-41.1157, 22.3885) -> (-36.4994, 34.1766)
  line L11 (36.1766, -13.9983) -> (41.4655, -13.9983)
  line L12 (21.1171, 12.5017) -> (21.1171, 9.2275)
  line L13 (-20.1418, 27.825) -> (-23.4161, 27.825)
  line L14 (-14.9161, 41.4655) -> (-14.9161, 35.8845)
  line L15 (3.0839, 35.8845) -> (3.0839, 41.4655)
  line L16 (11.5839, 27.825) -> (8.3097, 27.825)
  line L17 (8.3097, 20.825) -> (11.5839, 20.825)
  line L18 (28.1171, 9.2275) -> (28.1171, 12.5017)
  line L19 (-23.4161, 20.825) -> (-20.1418, 20.825)
  line L20 (41.4655, 4.0017) -> (36.1766, 4.0017)
  line L21 (3.0839, 41.4655) -> (24.1231, 41.4655)
  line L22 (41.4655, -13.9983) -> (41.4655, -20.5361)
  line L23 (28.1171, -22.4983) -> (28.1171, -19.2241)
  line L24 (21.1171, -19.2241) -> (21.1171, -22.4983)
  arc A1 centre (-36.3855, 20.5361) radius 5.08 clockwise from (-41.4365, 21.0784) to (-41.1157, 22.3885)
  arc A2 centre (-28.9018, -28.9018) radius 12.5637 clockwise from (-28.9018, -41.4655) to (-41.4655, -28.9018)
  arc A3 centre (21.3665, -36.3855) radius 5.08 clockwise from (23.2139, -41.1177) to (21.9088, -41.4365)
  arc A4 centre (31.7692, -32.3242) radius 5.08 clockwise from (36.4994, -34.1766) to (33.6166, -37.0564)
  arc A5 centre (36.3855, -20.5361) radius 5.08 clockwise from (41.4655, -20.5361) to (41.1157, -22.3885)
  arc A6 centre (36.3855, 20.5361) radius 5.08 clockwise from (41.1157, 22.3885) to (41.4655, 20.5361)
  arc A7 centre (31.7692, 32.3242) radius 5.08 clockwise from (33.6166, 37.0564) to (36.4994, 34.1766)
  arc A8 centre (24.1231, 36.3855) radius 5.08 clockwise from (24.1231, 41.4655) to (26.5251, 40.8618)
  arc A9 centre (-24.1331, 36.3855) radius 5.08 clockwise from (-26.5185, 40.8706) to (-24.1331, 41.4655)
  arc A10 centre (-31.7692, 32.3242) radius 5.08 clockwise from (-36.4994, 34.1766) to (-34.1546, 36.8093)
  circle C1 centre (18.76, -36.96) radius 1
  circle C2 centre (-31.4309, 31.4309) radius 2.159
  circle C3 centre (18.76, 36.96) radius 1
  circle C4 centre (-18.76, 36.96) radius 1
  circle C5 centre (31.4309, -31.4309) radius 2.159
  circle C6 centre (31.4309, 31.4309) radius 2.159
  arc A11 centre (24.6171, -4.9983) radius 14.65 clockwise from (21.1171, -19.2241) to (21.1171, 9.2275)
  arc A12 centre (24.6171, -22.4983) radius 3.5 clockwise from (28.1171, -22.4983) to (21.1171, -22.4983)
  arc A13 centre (24.6171, 12.5017) radius 3.5 clockwise from (21.1171, 12.5017) to (28.1171, 12.5017)
  arc A14 centre (-23.4161, 24.325) radius 3.5 clockwise from (-23.4161, 20.825) to (-23.4161, 27.825)
  arc A15 centre (11.5839, 24.325) radius 3.5 clockwise from (11.5839, 27.825) to (11.5839, 20.825)
  arc A16 centre (-5.9161, 24.325) radius 14.65 clockwise from (8.3097, 20.825) to (-20.1418, 20.825)
  circle C7 centre (-18.76, 36.96) radius 4.0817
  circle C8 centre (18.76, 36.96) radius 3.75
  circle C9 centre (36.96, 18.76) radius 3.75
  circle C10 centre (36.96, -18.76) radius 3.75
  circle C11 centre (18.76, -36.96) radius 3.75
  circle C12 centre (-37.3525, -16.6048) radius 3.75
  circle C13 centre (-17.3319, -36.9825) radius 3.75
  circle C14 centre (-37.3525, -16.6048) radius 1
  circle C15 centre (-17.3319, -36.9825) radius 1
  circle C16 centre (-36.96, 18.76) radius 1
  arc A17 centre (-5.9161, 24.325) radius 14.65 clockwise from (-20.1418, 27.825) to (-14.9161, 35.8845)
  circle C17 centre (-17.5539, 7.1948) radius 1.4
  circle C18 centre (0, 0) radius 5
  circle C19 centre (7.1948, -17.5539) radius 1.4
  arc A18 centre (24.6171, -4.9983) radius 14.65 clockwise from (28.1171, 9.2275) to (36.1766, 4.0017)
  circle C20 centre (36.96, -18.76) radius 1
  circle C21 centre (36.96, 18.76) radius 1
  arc A19 centre (-5.9161, 24.325) radius 14.65 clockwise from (3.0839, 35.8845) to (8.3097, 27.825)
  arc A20 centre (24.6171, -4.9983) radius 14.65 clockwise from (36.1766, -13.9983) to (28.1171, -19.2241)
  circle C22 centre (-36.96, 18.76) radius 3.75
  circle C23 centre (-30.9023, -30.9023) radius 5.5
  point P69 (36.96, -18.76)
  point P87 (36.96, -18.76)
  point P68 (36.96, 18.76)
  point P88 (36.96, 18.76)
  point P1 (0, 0)
  point P72 (-37.3525, -16.6048)
  point P73 (-17.3319, -36.9825)
  concentric C4 C7
  concentric C3 C8
  concentric C1 C11
  equal C8 C9
  equal C9 C10
  equal C10 C11
  concentric C12 C14
  concentric C13 C15
  equal C14 C15
  equal C1 C14
  equal C11 C12
  coincident P69 P87
  coincident P68 P88
  concentric C16 C22
  equal C13 C22
  dimension "d182" diameter C8 = 7.5
  dimension "d282" distance P1 P72 = 16.6048 (= "18.6048175707 mm - 2 mm")
  dimension "d283" distance P1 P72 = 37.3525
  dimension "d284" distance P1 P73 = 17.3319 (= "19.3319078447 mm - 2 mm")
  dimension "d285" distance P1 P73 = 36.9825
extrude "Extrude11" add sketch "Standoffs" profile of C3 C8 C10 C13 C15 C16 C20 C22 to an object
sketch "Sketch3" plane through (0, 7.5, 0) normal (0, 1, 0) x axis (-1, 0, 0)
  line L1 (34.2911, -40.6615) -> (34.2494, -40.8546)
  line L2 (34.3271, -40.4546) -> (34.2911, -40.6615)
  line L3 (34.3524, -40.2628) -> (34.3271, -40.4546)
  line L4 (34.3683, -40.0843) -> (34.3524, -40.2628)
  line L5 (34.3759, -39.9219) -> (34.3683, -40.0843)
  line L6 (34.3767, -39.7752) -> (34.3759, -39.9219)
  line L7 (34.3718, -39.6425) -> (34.3767, -39.7752)
  line L8 (34.3627, -39.5273) -> (34.3718, -39.6425)
  line L9 (34.3507, -39.428) -> (34.3627, -39.5273)
  line L10 (34.337, -39.3443) -> (34.3507, -39.428)
  line L11 (34.3101, -39.2249) -> (34.337, -39.3443)
  line L12 (34.2565, -39.0642) -> (34.3101, -39.2249)
  line L13 (34.2309, -38.9598) -> (34.2565, -39.0642)
  line L14 (34.2194, -38.8679) -> (34.2309, -38.9598)
  line L15 (34.2186, -38.827) -> (34.2194, -38.8679)
  line L16 (34.2208, -38.7896) -> (34.2186, -38.827)
  line L17 (34.226, -38.7559) -> (34.2208, -38.7896)
  line L18 (34.234, -38.7258) -> (34.226, -38.7559)
  line L19 (34.2447, -38.6996) -> (34.234, -38.7258)
  line L20 (34.2578, -38.6773) -> (34.2447, -38.6996)
  line L21 (34.2732, -38.659) -> (34.2578, -38.6773)
  line L22 (34.2908, -38.6448) -> (34.2732, -38.659)
  line L23 (34.3054, -38.6369) -> (34.2908, -38.6448)
  line L24 (34.4515, -38.571) -> (34.3054, -38.6369)
  line L25 (34.631, -38.4853) -> (34.4515, -38.571)
  line L26 (34.8085, -38.3954) -> (34.631, -38.4853)
  line L27 (34.9499, -38.32) -> (34.8085, -38.3954)
  line L28 (34.9651, -38.3133) -> (34.9499, -38.32)
  line L29 (34.9871, -38.308) -> (34.9651, -38.3133)
  line L30 (35.011, -38.307) -> (34.9871, -38.308)
  line L31 (35.0366, -38.3102) -> (35.011, -38.307)
  line L32 (35.0639, -38.3178) -> (35.0366, -38.3102)
  line L33 (35.0926, -38.3298) -> (35.0639, -38.3178)
  line L34 (35.1225, -38.3463) -> (35.0926, -38.3298)
  line L35 (35.1535, -38.3673) -> (35.1225, -38.3463)
  line L36 (35.1854, -38.3929) -> (35.1535, -38.3673)
  line L37 (35.2511, -38.4581) -> (35.1854, -38.3929)
  line L38 (35.3181, -38.5422) -> (35.2511, -38.4581)
  line L39 (35.4127, -38.6828) -> (35.3181, -38.5422)
  line L40 (35.4908, -38.777) -> (35.4127, -38.6828)
  line L41 (35.5488, -38.8389) -> (35.4908, -38.777)
  line L42 (35.6201, -38.9091) -> (35.5488, -38.8389)
  line L43 (35.7057, -38.9865) -> (35.6201, -38.9091)
  line L44 (35.8078, -39.0714) -> (35.7057, -38.9865)
  line L45 (35.9245, -39.1604) -> (35.8078, -39.0714)
  line L46 (36.0578, -39.2535) -> (35.9245, -39.1604)
  line L47 (36.2088, -39.3499) -> (36.0578, -39.2535)
  line L48 (36.3762, -39.4471) -> (36.2088, -39.3499)
  line L49 (36.562, -39.5449) -> (36.3762, -39.4471)
  line L50 (36.7404, -39.6298) -> (36.562, -39.5449)
  line L51 (37.2763, -39.0324) -> (37.2996, -39.2286)
  line L52 (37.2432, -38.825) -> (37.2763, -39.0324)
  line L53 (37.2047, -38.6354) -> (37.2432, -38.825)
  line L54 (37.1618, -38.4614) -> (37.2047, -38.6354)
  line L55 (37.1163, -38.3054) -> (37.1618, -38.4614)
  line L56 (37.0694, -38.1663) -> (37.1163, -38.3054)
  line L57 (37.0217, -38.0424) -> (37.0694, -38.1663)
  line L58 (36.9757, -37.9364) -> (37.0217, -38.0424)
  line L59 (36.9321, -37.8464) -> (36.9757, -37.9364)
  line L60 (36.892, -37.7717) -> (36.9321, -37.8464)
  line L61 (36.8278, -37.6675) -> (36.892, -37.7717)
  line L62 (36.7249, -37.5329) -> (36.8278, -37.6675)
  line L63 (36.6668, -37.4424) -> (36.7249, -37.5329)
  line L64 (36.6261, -37.3593) -> (36.6668, -37.4424)
  line L65 (36.612, -37.3209) -> (36.6261, -37.3593)
  line L66 (36.602, -37.2848) -> (36.612, -37.3209)
  line L67 (36.5959, -37.2512) -> (36.602, -37.2848)
  line L68 (36.5938, -37.2202) -> (36.5959, -37.2512)
  line L69 (36.5953, -37.1919) -> (36.5938, -37.2202)
  line L70 (36.6005, -37.1665) -> (36.5953, -37.1919)
  line L71 (36.6091, -37.1442) -> (36.6005, -37.1665)
  line L72 (36.6212, -37.1251) -> (36.6091, -37.1442)
  line L73 (36.6324, -37.1129) -> (36.6212, -37.1251)
  line L74 (36.7492, -37.0031) -> (36.6324, -37.1129)
  line L75 (36.8911, -36.8637) -> (36.7492, -37.0031)
  line L76 (37.0298, -36.7211) -> (36.8911, -36.8637)
  line L77 (37.1391, -36.6038) -> (37.0298, -36.7211)
  line L78 (37.1512, -36.5926) -> (37.1391, -36.6038)
  line L79 (37.1703, -36.5805) -> (37.1512, -36.5926)
  line L80 (37.1926, -36.5717) -> (37.1703, -36.5805)
  line L81 (37.2179, -36.5664) -> (37.1926, -36.5717)
  line L82 (37.2462, -36.5647) -> (37.2179, -36.5664)
  line L83 (37.2772, -36.5668) -> (37.2462, -36.5647)
  line L84 (37.3109, -36.5727) -> (37.2772, -36.5668)
  line L85 (37.347, -36.5825) -> (37.3109, -36.5727)
  line L86 (37.3855, -36.5964) -> (37.347, -36.5825)
  line L87 (37.4688, -36.6367) -> (37.3855, -36.5964)
  line L88 (37.5595, -36.6944) -> (37.4688, -36.6367)
  line L89 (37.6946, -36.7967) -> (37.5595, -36.6944)
  line L90 (37.7991, -36.8605) -> (37.6946, -36.7967)
  line L91 (37.874, -36.9002) -> (37.7991, -36.8605)
  line L92 (37.9642, -36.9434) -> (37.874, -36.9002)
  line L93 (38.0704, -36.9889) -> (37.9642, -36.9434)
  line L94 (38.1945, -37.036) -> (38.0704, -36.9889)
  line L95 (38.3338, -37.0823) -> (38.1945, -37.036)
  line L96 (38.49, -37.1271) -> (38.3338, -37.0823)
  line L97 (38.6642, -37.1692) -> (38.49, -37.1271)
  line L98 (38.854, -37.2068) -> (38.6642, -37.1692)
  line L99 (39.0616, -37.2389) -> (38.854, -37.2068)
  line L100 (39.2579, -37.2613) -> (39.0616, -37.2389)
  line L101 (39.5707, -36.5223) -> (39.6565, -36.7003)
  line L102 (39.4721, -36.3369) -> (39.5707, -36.5223)
  line L103 (39.3741, -36.17) -> (39.4721, -36.3369)
  line L104 (39.277, -36.0194) -> (39.3741, -36.17)
  line L105 (39.1834, -35.8866) -> (39.277, -36.0194)
  line L106 (39.0938, -35.7703) -> (39.1834, -35.8866)
  line L107 (39.0085, -35.6686) -> (39.0938, -35.7703)
  line L108 (38.9306, -35.5833) -> (39.0085, -35.6686)
  line L109 (38.8601, -35.5123) -> (38.9306, -35.5833)
  line L110 (38.7979, -35.4547) -> (38.8601, -35.5123)
  line L111 (38.7033, -35.377) -> (38.7979, -35.4547)
  line L112 (38.5623, -35.283) -> (38.7033, -35.377)
  line L113 (38.478, -35.2164) -> (38.5623, -35.283)
  line L114 (38.4125, -35.151) -> (38.478, -35.2164)
  line L115 (38.3867, -35.1192) -> (38.4125, -35.151)
  line L116 (38.3655, -35.0883) -> (38.3867, -35.1192)
  line L117 (38.3489, -35.0585) -> (38.3655, -35.0883)
  line L118 (38.3368, -35.0299) -> (38.3489, -35.0585)
  line L119 (38.329, -35.0026) -> (38.3368, -35.0299)
  line L120 (38.3257, -34.977) -> (38.329, -35.0026)
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  dimension "d185" distance = 0.15
  dimension "d221" diameter = 13
extrude "Extrude2" add sketch "Sketch3" to an object offset -10
hole "Hole1" HoleDepth 12.3382 HoleDiameter 2.8 TipAngle 180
